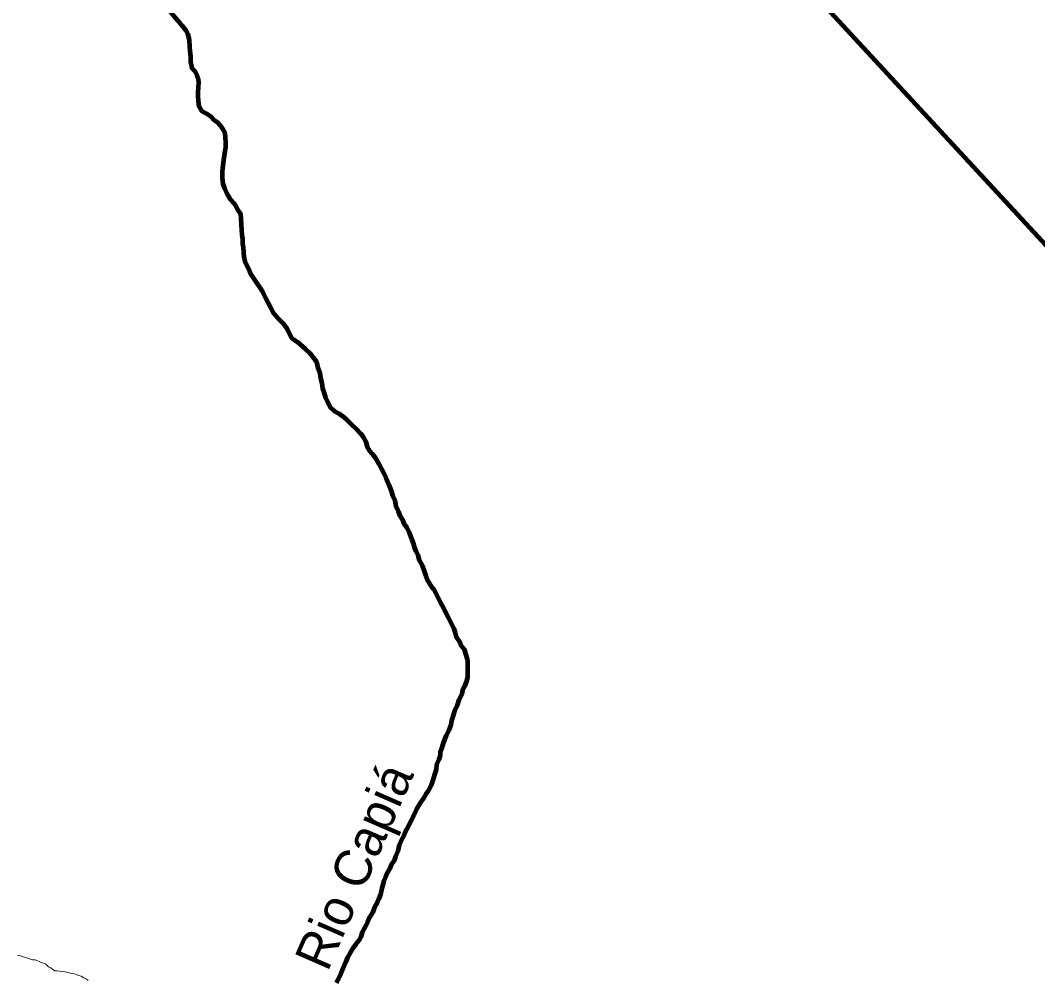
# Model space of a CAD drawing. Extents: x 553962 to 842807, y 8883888 to 9032388.
# Drawn here: x 643403 to 657184, y 8933785 to 8946781 of the extents above; entities that cross this region are included whole.
import ezdxf
from ezdxf.enums import TextEntityAlignment as Align

# ---------------------------------------------------------------- set-up
doc = ezdxf.new("R2010")
doc.units = 0
doc.header["$LTSCALE"] = 200
for name, color, linetype, lineweight in [('24', 7, 'Continuous', 25), ('25', 7, 'Continuous', 13), ('9', 7, 'Continuous', 90)]:
    doc.layers.add(name, color=color, linetype=linetype, lineweight=lineweight)
doc.layers.add('49', color=7, linetype='Continuous')

msp = doc.modelspace()

# ---------------------------------------------------------------- linework, layer by layer
at = {"layer": '24', "lineweight": 53}
for points in [[(645796.4, 8947834.9), (645776, 8947756.1), (645745.7, 8947693.7), (645725.4, 8947636.3), (645695.1, 8947568.9), (645674.8, 8947521.4), (645649.6, 8947474), (645596.7, 8947399.3), (645571.5, 8947356.9), (645541.2, 8947317), (645511, 8947272.1), (645475.8, 8947229.8), (645437.9, 8947162.4), (645412.7, 8947110), (645409.8, 8947032.5), (645409.4, 8946954.9), (645431.6, 8946894.8), (645476.4, 8946847), (645541.1, 8946774.1), (645593.3, 8946706.3), (645643.1, 8946643.5), (645668.8, 8946601.4)], [(645668.8, 8946601.4), (645692.5, 8946518.2), (645694.6, 8946428.1), (645699.3, 8946363), (645706.4, 8946292.9), (645706.1, 8946220.4), (645728.2, 8946132.7), (645765.5, 8946092.5), (645792.8, 8946037.3), (645812.6, 8945992.2), (645814.8, 8945939.6), (645812, 8945874.6), (645809.1, 8945802.1), (645808.9, 8945752), (645813.6, 8945684.5), (645820.8, 8945616.9), (645855.5, 8945556.7), (645925.1, 8945520.2)], [(645925.1, 8945520.2), (645980.3, 8945480.9), (646030.3, 8945430.9), (646080.3, 8945396.3), (646111.1, 8945361.7), (646137.1, 8945322.6), (646171.8, 8945257.3), (646176.4, 8945189.8), (646181.1, 8945124.7), (646180.8, 8945062.1), (646173.1, 8945007.1), (646162.8, 8944947.2), (646155, 8944897.2), (646149.8, 8944847.1), (646141.9, 8944777.1), (646139.2, 8944722.1), (646138.8, 8944644.6), (646145.9, 8944567), (646168.2, 8944506.8), (646200.3, 8944434.1), (646247.5, 8944358.8), (646299.8, 8944301), (646309, 8944284.7)], [(646309, 8944284.7), (646346.9, 8944218.2), (646384.2, 8944160.4), (646391.3, 8944097.8), (646395.9, 8944012.8), (646398.1, 8943942.7), (646405.3, 8943872.6), (646412.5, 8943820), (646414.7, 8943755), (646419.5, 8943702.4), (646424.2, 8943637.3), (646428.9, 8943577.3), (646446.1, 8943512.1), (646475.8, 8943444.4), (646508, 8943389.2), (646527.8, 8943344.1), (646562.6, 8943288.9), (646604.8, 8943221.1), (646647, 8943160.8), (646684.3, 8943105.6), (646721.5, 8943027.8), (646756.1, 8942957.6), (646790.8, 8942889.9), (646825.6, 8942829.7), (646865.4, 8942779.4), (646902.7, 8942731.7), (646957.4, 8942676.4), (647012.1, 8942606), (647046.8, 8942538.3), (647076.6, 8942480.6), (647102.9, 8942459), (647151.9, 8942424.7), (647151.9, 8942424.7), (647259.8, 8942331.6), (647323.5, 8942272.8), (647367.7, 8942218.9), (647416.7, 8942155.2), (647431.4, 8942071.9), (647460.8, 8942003.3), (647470.7, 8941934.7), (647485.4, 8941866.1), (647498.6, 8941792.9), (647513.3, 8941742.8), (647538, 8941665.1), (647557.8, 8941619.9), (647597.5, 8941547.2), (647657.2, 8941484.3), (647722.1, 8941454), (647762, 8941421.2), (647826.8, 8941368.3), (647896.5, 8941297.9), (647948.8, 8941250.1), (648011, 8941182.2), (648043.4, 8941142.1), (648083.1, 8941071.8), (648100.2, 8941001.6), (648132.5, 8940948.9), (648170.9, 8940907.9), (648214.2, 8940849.2), (648257.5, 8940775), (648294.6, 8940700.8), (648325.5, 8940642.1), (648353.4, 8940586.5), (648378.1, 8940533.9), (648399.8, 8940478.3), (648430.7, 8940394.8), (648446.2, 8940342.3), (648474, 8940274.3), (648489.2, 8940201.5), (648521.4, 8940133.8), (648546.1, 8940073.6), (648581.1, 8940014.6), (648600.6, 8939953.5), (648636.7, 8939906.2), (648667.3, 8939850.6), (648703.5, 8939758.8), (648725.8, 8939700.4), (648739.7, 8939647.6), (648762, 8939592), (648787, 8939533.6), (648806.5, 8939466.9), (648845.4, 8939394.6), (648873.2, 8939316.7), (648898.3, 8939255.5), (648922.2, 8939185.9), (648969.4, 8939115.6), (649001.7, 8939077.9), (649063.7, 8938952.5), (649095.9, 8938889.7), (649130.6, 8938824.5), (649157.8, 8938769.3), (649200, 8938691.5), (649276.8, 8938536), (649291.6, 8938483.4), (649308.8, 8938428.2), (649356, 8938355.4), (649380.8, 8938302.8), (649415.6, 8938260), (649432.8, 8938197.4), (649457.5, 8938124.7), (649458.7, 8938112.5)], [(649458.7, 8938112.5), (649462.3, 8938074.6), (649461.7, 8937947), (649458.9, 8937884.5), (649441, 8937814.5), (649418.2, 8937754.6), (649393, 8937709.7), (649382.7, 8937654.7), (649342.3, 8937574.8), (649321.9, 8937502.4), (649286.6, 8937427.5), (649266.2, 8937362.5), (649243.4, 8937297.6), (649233.1, 8937237.6), (649207.7, 8937165.2), (649172.4, 8937090.3), (649131.8, 8936990.4), (649111.5, 8936927.9), (649091.2, 8936868), (649088.5, 8936820.5), (649070.7, 8936768), (649042.9, 8936693.1), (649035.1, 8936630.6), (649014.7, 8936565.6), (648986.8, 8936473.2), (648966.5, 8936418.2), (648928.6, 8936343.4), (648898.4, 8936298.5), (648858, 8936233.6), (648830.3, 8936188.7), (648774.8, 8936103.9), (648736.9, 8936024.1), (648704.1, 8935954.2), (648671.2, 8935886.8), (648635.9, 8935819.4), (648605.6, 8935757), (648582.3, 8935707.9)], [(648582.3, 8935707.9), (648534.8, 8935604.7), (648516.9, 8935524.8), (648484, 8935454.9), (648466.2, 8935397.4), (648428.4, 8935342.6), (648410.7, 8935290.1), (648377.9, 8935235.2), (648347.6, 8935175.3), (648327.3, 8935125.4), (648299.3, 8935022.9), (648281.4, 8934937.9), (648258.6, 8934878), (648238.3, 8934825.6), (648200.5, 8934765.7), (648180.2, 8934700.8), (648132.3, 8934628.4), (648104.5, 8934563.5), (648085.8, 8934528.5)], [(648085.8, 8934528.5), (648033.8, 8934426.2), (648013.5, 8934366.3), (647988.2, 8934313.9), (647947.9, 8934264), (647910.1, 8934214.2), (647874.8, 8934156.8), (647837, 8934086.9), (647811.7, 8934027), (647776.2, 8933942.1), (647745.8, 8933864.7), (647682.7, 8933739.9)]]:
    msp.add_lwpolyline(points, dxfattribs=at)
at = {"layer": '25'}
msp.add_lwpolyline([(643363.1, 8934114.1), (643405.6, 8934108.8), (643440.5, 8934096.1), (643477.9, 8934083.3), (643500.4, 8934075.7), (643542.8, 8934060.4), (643567.8, 8934055.2), (643602.8, 8934052.5), (643647.6, 8934034.7), (643685, 8934019.4), (643717.5, 8934009.2), (643749.9, 8933993.9), (643784.6, 8933958.6), (643814.5, 8933943.4), (643836.9, 8933925.7), (643871.7, 8933903), (643899.2, 8933902.8), (643936.7, 8933900.1), (643971.7, 8933897.3), (644004.2, 8933892.1), (644026.7, 8933884.4), (644066.6, 8933876.7), (644096.6, 8933868.9), (644136.6, 8933863.7), (644161.5, 8933856), (644196.4, 8933843.2), (644226.3, 8933830.5), (644263.7, 8933810.3), (644301.1, 8933790), (644323.4, 8933772.3)], dxfattribs=at)
at = {"layer": '9'}
for points in [[(645793.1, 8949290.9), (653495.4, 8947850), (659002.1, 8941889), (662654, 8939737.7), (668185.2, 8933928.8)], [(645796.4, 8947834.9), (645776, 8947756.1), (645745.7, 8947693.7), (645725.4, 8947636.3), (645695.1, 8947568.9), (645674.8, 8947521.4), (645649.6, 8947474), (645596.7, 8947399.3), (645571.5, 8947356.9), (645541.2, 8947317), (645511, 8947272.1), (645475.8, 8947229.8), (645437.9, 8947162.4), (645412.7, 8947110), (645409.8, 8947032.5), (645409.4, 8946954.9), (645431.6, 8946894.8), (645476.4, 8946847), (645541.1, 8946774.1), (645593.3, 8946706.3), (645643.1, 8946643.5), (645668.8, 8946601.4)], [(645668.8, 8946601.4), (645692.5, 8946518.2), (645694.6, 8946428.1), (645699.3, 8946363), (645706.4, 8946292.9), (645706.1, 8946220.4), (645728.2, 8946132.7), (645765.5, 8946092.5), (645792.8, 8946037.3), (645812.6, 8945992.2), (645814.8, 8945939.6), (645812, 8945874.6), (645809.1, 8945802.1), (645808.9, 8945752), (645813.6, 8945684.5), (645820.8, 8945616.9), (645855.5, 8945556.7), (645925.1, 8945520.2)], [(645925.1, 8945520.2), (645980.3, 8945480.9), (646030.3, 8945430.9), (646080.3, 8945396.3), (646111.1, 8945361.7), (646137.1, 8945322.6), (646171.8, 8945257.3), (646176.4, 8945189.8), (646181.1, 8945124.7), (646180.8, 8945062.1), (646173.1, 8945007.1), (646162.8, 8944947.2), (646155, 8944897.2), (646149.8, 8944847.1), (646141.9, 8944777.1), (646139.2, 8944722.1), (646138.8, 8944644.6), (646145.9, 8944567), (646168.2, 8944506.8), (646200.3, 8944434.1), (646247.5, 8944358.8), (646299.8, 8944301), (646309, 8944284.7)], [(646309, 8944284.7), (646346.9, 8944218.2), (646384.2, 8944160.4), (646391.3, 8944097.8), (646395.9, 8944012.8), (646398.1, 8943942.7), (646405.3, 8943872.6), (646412.5, 8943820), (646414.7, 8943755), (646419.5, 8943702.4), (646424.2, 8943637.3), (646428.9, 8943577.3), (646446.1, 8943512.1), (646475.8, 8943444.4), (646508, 8943389.2), (646527.8, 8943344.1), (646562.6, 8943288.9), (646604.8, 8943221.1), (646647, 8943160.8), (646684.3, 8943105.6), (646721.5, 8943027.8), (646756.1, 8942957.6), (646790.8, 8942889.9), (646825.6, 8942829.7), (646865.4, 8942779.4), (646902.7, 8942731.7), (646957.4, 8942676.4), (647012.1, 8942606), (647046.8, 8942538.3), (647076.6, 8942480.6), (647102.9, 8942459), (647151.9, 8942424.7), (647151.9, 8942424.7), (647259.8, 8942331.6), (647323.5, 8942272.8), (647367.7, 8942218.9), (647416.7, 8942155.2), (647431.4, 8942071.9), (647460.8, 8942003.3), (647470.7, 8941934.7), (647485.4, 8941866.1), (647498.6, 8941792.9), (647513.3, 8941742.8), (647538, 8941665.1), (647557.8, 8941619.9), (647597.5, 8941547.2), (647657.2, 8941484.3), (647722.1, 8941454), (647762, 8941421.2), (647826.8, 8941368.3), (647896.5, 8941297.9), (647948.8, 8941250.1), (648011, 8941182.2), (648043.4, 8941142.1), (648083.1, 8941071.8), (648100.2, 8941001.6), (648132.5, 8940948.9), (648170.9, 8940907.9), (648214.2, 8940849.2), (648257.5, 8940775), (648294.6, 8940700.8), (648325.5, 8940642.1), (648353.4, 8940586.5), (648378.1, 8940533.9), (648399.8, 8940478.3), (648430.7, 8940394.8), (648446.2, 8940342.3), (648474, 8940274.3), (648489.2, 8940201.5), (648521.4, 8940133.8), (648546.1, 8940073.6), (648581.1, 8940014.6), (648600.6, 8939953.5), (648636.7, 8939906.2), (648667.3, 8939850.6), (648703.5, 8939758.8), (648725.8, 8939700.4), (648739.7, 8939647.6), (648762, 8939592), (648787, 8939533.6), (648806.5, 8939466.9), (648845.4, 8939394.6), (648873.2, 8939316.7), (648898.3, 8939255.5), (648922.2, 8939185.9), (648969.4, 8939115.6), (649001.7, 8939077.9), (649063.7, 8938952.5), (649095.9, 8938889.7), (649130.6, 8938824.5), (649157.8, 8938769.3), (649200, 8938691.5), (649276.8, 8938536), (649291.6, 8938483.4), (649308.8, 8938428.2), (649356, 8938355.4), (649380.8, 8938302.8), (649415.6, 8938260), (649432.8, 8938197.4), (649457.5, 8938124.7), (649458.7, 8938112.5)], [(649458.7, 8938112.5), (649462.3, 8938074.6), (649461.7, 8937947), (649458.9, 8937884.5), (649441, 8937814.5), (649418.2, 8937754.6), (649393, 8937709.7), (649382.7, 8937654.7), (649342.3, 8937574.8), (649321.9, 8937502.4), (649286.6, 8937427.5), (649266.2, 8937362.5), (649243.4, 8937297.6), (649233.1, 8937237.6), (649207.7, 8937165.2), (649172.4, 8937090.3), (649131.8, 8936990.4), (649111.5, 8936927.9), (649091.2, 8936868), (649088.5, 8936820.5), (649070.7, 8936768), (649042.9, 8936693.1), (649035.1, 8936630.6), (649014.7, 8936565.6), (648986.8, 8936473.2), (648966.5, 8936418.2), (648928.6, 8936343.4), (648898.4, 8936298.5), (648858, 8936233.6), (648830.3, 8936188.7), (648774.8, 8936103.9), (648736.9, 8936024.1), (648704.1, 8935954.2), (648671.2, 8935886.8), (648635.9, 8935819.4), (648605.6, 8935757), (648582.3, 8935707.9)], [(648582.3, 8935707.9), (648534.8, 8935604.7), (648516.9, 8935524.8), (648484, 8935454.9), (648466.2, 8935397.4), (648428.4, 8935342.6), (648410.7, 8935290.1), (648377.9, 8935235.2), (648347.6, 8935175.3), (648327.3, 8935125.4), (648299.3, 8935022.9), (648281.4, 8934937.9), (648258.6, 8934878), (648238.3, 8934825.6), (648200.5, 8934765.7), (648180.2, 8934700.8), (648132.3, 8934628.4), (648104.5, 8934563.5), (648085.8, 8934528.5)], [(648085.8, 8934528.5), (648033.8, 8934426.2), (648013.5, 8934366.3), (647988.2, 8934313.9), (647947.9, 8934264), (647910.1, 8934214.2), (647874.8, 8934156.8), (647837, 8934086.9), (647811.7, 8934027), (647776.2, 8933942.1), (647745.8, 8933864.7), (647682.7, 8933739.9)]]:
    msp.add_lwpolyline(points, dxfattribs=at)
msp.add_spline([(637260.6, 8972975.8), (641524.5, 8971056.2), (652526.1, 8965412.7), (653164.3, 8965062.8), (670790.5, 8953770.1), (686194, 8943929.9), (696283.3, 8937647.1)], degree=3, dxfattribs=at)

# ---------------------------------------------------------------- texts
at = {"layer": '49'}
msp.add_text('Rio Capiá', height=500, rotation=66.381, dxfattribs=at).set_placement((648152.9, 8935223.9), align=Align.CENTER)

doc.saveas('drawing.dxf')
